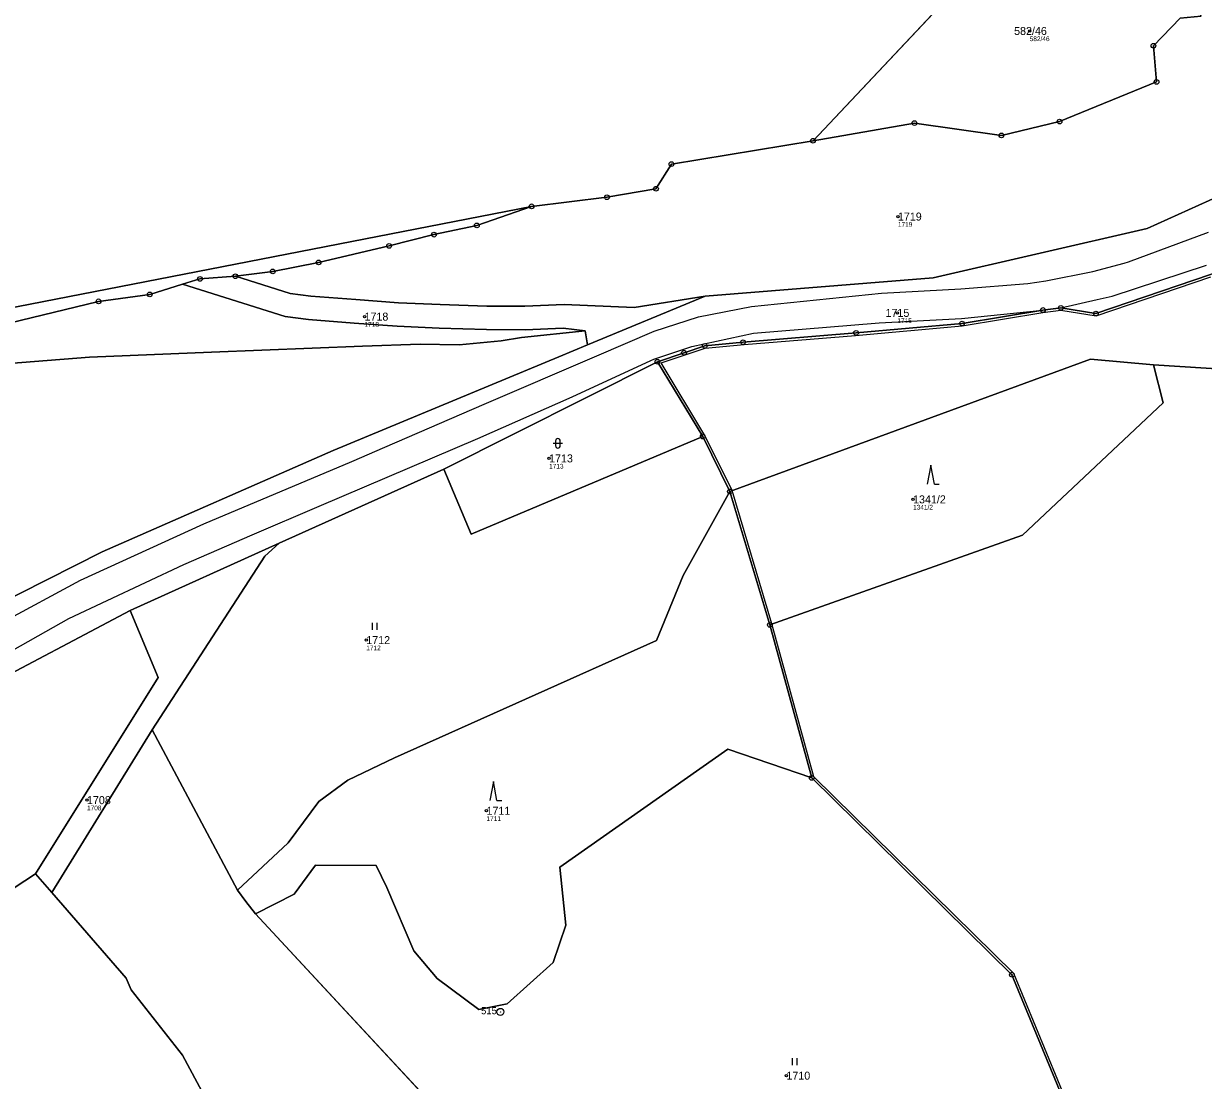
# Model space of a CAD drawing. Extents: x -770088 to -765625, y -1057899 to -1053934.
# Drawn here: x -768436.7 to -768186.2, y -1055836.3 to -1055611.9 of the extents above; entities that cross this region are included whole.
import ezdxf

# ---------------------------------------------------------------- set-up
doc = ezdxf.new("R2010")
doc.units = 0
for name, color, linetype in [('Definiční body', 7, 'Continuous'), ('Hranice parcel', 7, 'Continuous'), ('Parcelní čísla', 7, 'Continuous'), ('Polygon parcely', 7, 'Continuous'), ('Vnitřní kresba', 7, 'Continuous'), ('Značky bodu BP', 7, 'Continuous'), ('Značky kultur', 7, 'Continuous')]:
    doc.layers.add(name, color=color, linetype=linetype)

msp = doc.modelspace()

# ---------------------------------------------------------------- linework, layer by layer
at = {"layer": 'Definiční body'}
for centre in [(-768223.09, -1055613.47), (-768251.07, -1055652.87), (-768251.19, -1055673.32), (-768364.33, -1055674.11), (-768325.14, -1055704.21), (-768247.85, -1055712.91), (-768363.96, -1055742.79), (-768423.26, -1055776.76), (-768338.43, -1055779.02), (-768274.74, -1055835.25)]:
    msp.add_circle(centre, 0.25, dxfattribs=at)
at = {"layer": 'Hranice parcel'}
for p, q in [((-768269.09, -1055636.77), (-768215.72, -1055580.12)), ((-768498.28, -1055683.72), (-768328.85, -1055650.7)), ((-768292.03, -1055669.76), (-768317.01, -1055680.13)), ((-768317.01, -1055680.13), (-768317.48, -1055677.12)), ((-768302.12, -1055683.68), (-768347.5, -1055706.52)), ((-768292.5, -1055699.58), (-768302.12, -1055683.68)), ((-768286.73, -1055711.22), (-768292.5, -1055699.58)), ((-768347.5, -1055706.52), (-768382.42, -1055722.23)), ((-768278.26, -1055739.56), (-768286.73, -1055711.22)), ((-768382.42, -1055722.23), (-768414.12, -1055736.49)), ((-768269.37, -1055772.05), (-768278.26, -1055739.56)), ((-768430.74, -1055796.35), (-768409.4, -1055761.83)), ((-768391.29, -1055795.86), (-768409.4, -1055761.83)), ((-768430.74, -1055796.35), (-768434.17, -1055792.4)), ((-768284.6, -1055911.68), (-768387.49, -1055800.93))]:
    msp.add_line(p, q, dxfattribs=at)
for points in [[(-768196.77, -1055684.34), (-768179.99, -1055685.43), (-768149.61, -1055682.54), (-768104.29, -1055637.41), (-768086.16, -1055607.62), (-767983.52, -1055552.84)], [(-768112.56, -1055604.82), (-768160.87, -1055638.55), (-768198.11, -1055655.41), (-768243.55, -1055665.87), (-768292.03, -1055669.76)], [(-768186.69, -1055610.35), (-768191.13, -1055610.78), (-768196.8, -1055616.6), (-768196.16, -1055624.27), (-768216.73, -1055632.69), (-768229.08, -1055635.64), (-768247.55, -1055633.03), (-768269.09, -1055636.77)], [(-768269.09, -1055636.77), (-768299.15, -1055641.74), (-768302.44, -1055646.96), (-768312.87, -1055648.77), (-768328.85, -1055650.7)], [(-768328.85, -1055650.7), (-768340.48, -1055654.76), (-768349.59, -1055656.71), (-768359.11, -1055659.09), (-768374.07, -1055662.6), (-768383.82, -1055664.53), (-768391.75, -1055665.55)], [(-768391.75, -1055665.55), (-768399.27, -1055666.11), (-768402.98, -1055667.25)], [(-768292.03, -1055669.76), (-768307.07, -1055672.16), (-768321.97, -1055671.56), (-768330.29, -1055671.92), (-768338.37, -1055671.88), (-768348.27, -1055671.57), (-768357.12, -1055671.16), (-768366.16, -1055670.48), (-768375.73, -1055669.74), (-768380.15, -1055669.2), (-768391.75, -1055665.55)], [(-768302.12, -1055683.68), (-768296.49, -1055681.79), (-768292.08, -1055680.32), (-768283.96, -1055679.54), (-768259.94, -1055677.57), (-768237.46, -1055675.58), (-768220.27, -1055672.71), (-768216.46, -1055672.25), (-768209.02, -1055673.46), (-768184.7, -1055665.16)], [(-768402.98, -1055667.25), (-768409.93, -1055669.39), (-768420.8, -1055670.87), (-768439.77, -1055675.5), (-768449.48, -1055677.95), (-768458.49, -1055679.02), (-768472.89, -1055680.73), (-768484.05, -1055683.5), (-768494.16, -1055687.77), (-768494.99, -1055688.26)], [(-768317.48, -1055677.12), (-768322.16, -1055676.57), (-768330.19, -1055676.92), (-768338.46, -1055676.88), (-768348.46, -1055676.57), (-768357.42, -1055676.15), (-768366.53, -1055675.47), (-768376.22, -1055674.72), (-768381.21, -1055674.11), (-768402.98, -1055667.25)], [(-768317.48, -1055677.12), (-768331, -1055678.54), (-768335.32, -1055679.24), (-768344.25, -1055680.07), (-768352.52, -1055679.97), (-768364.76, -1055680.41), (-768396.85, -1055681.68), (-768422.75, -1055682.69), (-768446.13, -1055684.53), (-768460.76, -1055687.94), (-768468.57, -1055690.39), (-768479.04, -1055698.34), (-768510.04, -1055705.01), (-768532.57, -1055718.14), (-768547.75, -1055728.13), (-768565.83, -1055739.84), (-768576.52, -1055745.35), (-768590.86, -1055754.31), (-768615.09, -1055773.23), (-768625.74, -1055787.65)], [(-768317.01, -1055680.13), (-768323.05, -1055682.64), (-768370.97, -1055702.51), (-768420.02, -1055724.02), (-768455.1, -1055741.72), (-768489.08, -1055761.49)], [(-768286.73, -1055711.22), (-768210.16, -1055683.15), (-768196.77, -1055684.34)], [(-768196.77, -1055684.34), (-768194.75, -1055692.38), (-768224.62, -1055720.54), (-768278.26, -1055739.56)], [(-768292.5, -1055699.58), (-768341.68, -1055720.27), (-768347.5, -1055706.52)], [(-768286.73, -1055711.22), (-768296.68, -1055729.05), (-768302.3, -1055742.9), (-768357.96, -1055767.75), (-768367.84, -1055772.51), (-768374.05, -1055777.07), (-768380.51, -1055785.79), (-768391.29, -1055795.86)], [(-768409.4, -1055761.83), (-768385.51, -1055724.99), (-768382.42, -1055722.23)], [(-768414.12, -1055736.49), (-768446.8, -1055753.76), (-768482.2, -1055773.7)], [(-768434.17, -1055792.4), (-768408.16, -1055750.72), (-768414.12, -1055736.49)], [(-768269.37, -1055772.05), (-768287.2, -1055765.92), (-768322.86, -1055791.01), (-768321.57, -1055803.27), (-768324.27, -1055811.21), (-768334.05, -1055819.97), (-768340.04, -1055821.2), (-768348.88, -1055814.61), (-768353.84, -1055808.73), (-768359.61, -1055795.29), (-768361.87, -1055790.62), (-768374.77, -1055790.56), (-768379.26, -1055796.69), (-768387.49, -1055800.93)], [(-768284.6, -1055911.68), (-768256.62, -1055887.41), (-768222.04, -1055883.64), (-768196.97, -1055880.9), (-768208.15, -1055859.21), (-768226.85, -1055813.83), (-768269.37, -1055772.05)], [(-768434.17, -1055792.4), (-768525.18, -1055852.08), (-768616.18, -1055911.76)], [(-768387.49, -1055800.93), (-768389.5, -1055798.25), (-768391.29, -1055795.86)], [(-768301.36, -1055926.65), (-768319.56, -1055917.31), (-768324.83, -1055913.94), (-768331.1, -1055909.69), (-768346.54, -1055893.39), (-768362.81, -1055880.26), (-768375.98, -1055868.58), (-768387.42, -1055856.06), (-768394.12, -1055847.36), (-768402.95, -1055830.89), (-768413.85, -1055817.01), (-768414.95, -1055814.57), (-768430.74, -1055796.35)]]:
    msp.add_lwpolyline(points, dxfattribs=at)
at = {"layer": 'Polygon parcely'}
for points in [[(-768521.62, -1055538.69), (-768491.56, -1055616.88), (-768518.64, -1055655.58), (-768498.28, -1055683.72), (-768328.85, -1055650.7), (-768312.87, -1055648.77), (-768302.44, -1055646.96), (-768299.15, -1055641.74), (-768269.09, -1055636.77), (-768215.72, -1055580.12)], [(-768112.56, -1055604.82), (-768160.87, -1055638.55), (-768198.11, -1055655.41), (-768243.55, -1055665.87), (-768292.03, -1055669.76), (-768317.01, -1055680.13), (-768323.05, -1055682.64), (-768370.97, -1055702.51), (-768420.02, -1055724.02), (-768455.1, -1055741.72)], [(-768086.16, -1055607.62), (-768104.29, -1055637.41), (-768149.61, -1055682.54), (-768179.99, -1055685.43), (-768196.77, -1055684.34), (-768194.75, -1055692.38), (-768224.62, -1055720.54), (-768278.26, -1055739.56), (-768269.37, -1055772.05), (-768226.85, -1055813.83), (-768208.15, -1055859.21), (-768196.97, -1055880.9), (-768222.04, -1055883.64), (-768256.62, -1055887.41), (-768284.6, -1055911.68), (-768295.98, -1055921.55), (-768301.36, -1055926.65), (-768324.43, -1055938.67), (-768353.01, -1055951.04), (-768391.65, -1055965.9), (-768431.86, -1055976.92), (-768474.56, -1055997.15)], [(-768103.19, -1055610.16), (-768111.79, -1055616.51), (-768112.75, -1055629.19), (-768123.27, -1055644.97), (-768143.51, -1055660.46), (-768184.7, -1055665.16), (-768209.02, -1055673.46), (-768216.46, -1055672.25), (-768220.27, -1055672.71), (-768237.46, -1055675.58), (-768259.94, -1055677.57), (-768283.96, -1055679.54), (-768292.08, -1055680.32), (-768296.49, -1055681.79), (-768302.12, -1055683.68), (-768292.5, -1055699.58), (-768286.73, -1055711.22), (-768210.16, -1055683.15), (-768196.77, -1055684.34), (-768179.99, -1055685.43), (-768149.61, -1055682.54), (-768104.29, -1055637.41), (-768086.16, -1055607.62)], [(-768446.8, -1055753.76), (-768414.12, -1055736.49), (-768382.42, -1055722.23), (-768347.5, -1055706.52), (-768302.12, -1055683.68), (-768296.49, -1055681.79), (-768292.08, -1055680.32), (-768283.96, -1055679.54), (-768259.94, -1055677.57), (-768237.46, -1055675.58), (-768220.27, -1055672.71), (-768216.46, -1055672.25), (-768209.02, -1055673.46), (-768184.7, -1055665.16), (-768168.5, -1055657.24), (-768135.64, -1055636.25), (-768111.79, -1055616.51), (-768103.19, -1055610.16)], [(-768191.13, -1055610.78), (-768196.8, -1055616.6), (-768196.16, -1055624.27), (-768216.73, -1055632.69), (-768229.08, -1055635.64), (-768247.55, -1055633.03), (-768269.09, -1055636.77), (-768299.15, -1055641.74), (-768302.44, -1055646.96), (-768312.87, -1055648.77), (-768328.85, -1055650.7), (-768340.48, -1055654.76), (-768349.59, -1055656.71), (-768359.11, -1055659.09), (-768374.07, -1055662.6), (-768383.82, -1055664.53), (-768391.75, -1055665.55), (-768380.15, -1055669.2), (-768375.73, -1055669.74), (-768366.16, -1055670.48), (-768357.12, -1055671.16), (-768348.27, -1055671.57), (-768338.37, -1055671.88), (-768330.29, -1055671.92), (-768321.97, -1055671.56), (-768307.07, -1055672.16), (-768292.03, -1055669.76), (-768243.55, -1055665.87), (-768198.11, -1055655.41), (-768160.87, -1055638.55)], [(-768446.13, -1055684.53), (-768422.75, -1055682.69), (-768396.85, -1055681.68), (-768364.76, -1055680.41), (-768352.52, -1055679.97), (-768344.25, -1055680.07), (-768335.32, -1055679.24), (-768331, -1055678.54), (-768317.48, -1055677.12), (-768322.16, -1055676.57), (-768330.19, -1055676.92), (-768338.46, -1055676.88), (-768348.46, -1055676.57), (-768357.42, -1055676.15), (-768366.53, -1055675.47), (-768376.22, -1055674.72), (-768381.21, -1055674.11), (-768402.98, -1055667.25), (-768409.93, -1055669.39), (-768420.8, -1055670.87), (-768439.77, -1055675.5)], [(-768455.1, -1055741.72), (-768420.02, -1055724.02), (-768370.97, -1055702.51), (-768323.05, -1055682.64), (-768317.01, -1055680.13), (-768317.48, -1055677.12), (-768331, -1055678.54), (-768335.32, -1055679.24), (-768344.25, -1055680.07), (-768352.52, -1055679.97), (-768364.76, -1055680.41), (-768396.85, -1055681.68), (-768422.75, -1055682.69), (-768446.13, -1055684.53)], [(-768474.56, -1055997.15), (-768431.86, -1055976.92), (-768391.65, -1055965.9), (-768353.01, -1055951.04), (-768324.43, -1055938.67), (-768301.36, -1055926.65), (-768319.56, -1055917.31), (-768324.83, -1055913.94), (-768331.1, -1055909.69), (-768346.54, -1055893.39), (-768362.81, -1055880.26), (-768375.98, -1055868.58), (-768387.42, -1055856.06), (-768394.12, -1055847.36), (-768402.95, -1055830.89), (-768413.85, -1055817.01), (-768414.95, -1055814.57), (-768430.74, -1055796.35), (-768434.17, -1055792.4), (-768525.18, -1055852.08)]]:
    msp.add_lwpolyline(points, dxfattribs=at)
for points in [[(-768186.69, -1055610.35), (-768195.09, -1055591.48), (-768202.2, -1055590.14), (-768215.72, -1055580.12), (-768269.09, -1055636.77), (-768247.55, -1055633.03), (-768229.08, -1055635.64), (-768216.73, -1055632.69), (-768196.16, -1055624.27), (-768196.8, -1055616.6), (-768191.13, -1055610.78)], [(-768498.28, -1055683.72), (-768494.99, -1055688.26), (-768494.16, -1055687.77), (-768484.05, -1055683.5), (-768472.89, -1055680.73), (-768458.49, -1055679.02), (-768449.48, -1055677.95), (-768439.77, -1055675.5), (-768420.8, -1055670.87), (-768409.93, -1055669.39), (-768402.98, -1055667.25), (-768399.27, -1055666.11), (-768391.75, -1055665.55), (-768383.82, -1055664.53), (-768374.07, -1055662.6), (-768359.11, -1055659.09), (-768349.59, -1055656.71), (-768340.48, -1055654.76), (-768328.85, -1055650.7)], [(-768307.07, -1055672.16), (-768321.97, -1055671.56), (-768330.29, -1055671.92), (-768338.37, -1055671.88), (-768348.27, -1055671.57), (-768357.12, -1055671.16), (-768366.16, -1055670.48), (-768375.73, -1055669.74), (-768380.15, -1055669.2), (-768391.75, -1055665.55), (-768399.27, -1055666.11), (-768402.98, -1055667.25), (-768381.21, -1055674.11), (-768376.22, -1055674.72), (-768366.53, -1055675.47), (-768357.42, -1055676.15), (-768348.46, -1055676.57), (-768338.46, -1055676.88), (-768330.19, -1055676.92), (-768322.16, -1055676.57), (-768317.48, -1055677.12), (-768317.01, -1055680.13), (-768292.03, -1055669.76)], [(-768278.26, -1055739.56), (-768224.62, -1055720.54), (-768194.75, -1055692.38), (-768196.77, -1055684.34), (-768210.16, -1055683.15), (-768286.73, -1055711.22)], [(-768302.12, -1055683.68), (-768347.5, -1055706.52), (-768341.68, -1055720.27), (-768292.5, -1055699.58)], [(-768347.5, -1055706.52), (-768382.42, -1055722.23), (-768385.51, -1055724.99), (-768409.4, -1055761.83), (-768391.29, -1055795.86), (-768380.51, -1055785.79), (-768374.05, -1055777.07), (-768367.84, -1055772.51), (-768357.96, -1055767.75), (-768302.3, -1055742.9), (-768296.68, -1055729.05), (-768286.73, -1055711.22), (-768292.5, -1055699.58), (-768341.68, -1055720.27)], [(-768380.51, -1055785.79), (-768391.29, -1055795.86), (-768389.5, -1055798.25), (-768387.49, -1055800.93), (-768379.26, -1055796.69), (-768374.77, -1055790.56), (-768361.87, -1055790.62), (-768359.61, -1055795.29), (-768353.84, -1055808.73), (-768348.88, -1055814.61), (-768340.04, -1055821.2), (-768334.05, -1055819.97), (-768324.27, -1055811.21), (-768321.57, -1055803.27), (-768322.86, -1055791.01), (-768287.2, -1055765.92), (-768269.37, -1055772.05), (-768278.26, -1055739.56), (-768286.73, -1055711.22), (-768296.68, -1055729.05), (-768302.3, -1055742.9), (-768357.96, -1055767.75), (-768367.84, -1055772.51), (-768374.05, -1055777.07)], [(-768409.4, -1055761.83), (-768385.51, -1055724.99), (-768382.42, -1055722.23), (-768414.12, -1055736.49), (-768408.16, -1055750.72), (-768434.17, -1055792.4), (-768430.74, -1055796.35)], [(-768414.12, -1055736.49), (-768446.8, -1055753.76), (-768482.2, -1055773.7), (-768515.92, -1055792.7), (-768578.63, -1055829.2), (-768625.43, -1055857.79), (-768643.1, -1055869.51), (-768616.18, -1055911.76), (-768525.18, -1055852.08), (-768434.17, -1055792.4), (-768408.16, -1055750.72)], [(-768284.6, -1055911.68), (-768387.49, -1055800.93), (-768389.5, -1055798.25), (-768391.29, -1055795.86), (-768409.4, -1055761.83), (-768430.74, -1055796.35), (-768414.95, -1055814.57), (-768413.85, -1055817.01), (-768402.95, -1055830.89), (-768394.12, -1055847.36), (-768387.42, -1055856.06), (-768375.98, -1055868.58), (-768362.81, -1055880.26), (-768346.54, -1055893.39), (-768331.1, -1055909.69), (-768324.83, -1055913.94), (-768319.56, -1055917.31), (-768301.36, -1055926.65), (-768295.98, -1055921.55)], [(-768324.27, -1055811.21), (-768334.05, -1055819.97), (-768340.04, -1055821.2), (-768348.88, -1055814.61), (-768353.84, -1055808.73), (-768359.61, -1055795.29), (-768361.87, -1055790.62), (-768374.77, -1055790.56), (-768379.26, -1055796.69), (-768387.49, -1055800.93), (-768284.6, -1055911.68), (-768256.62, -1055887.41), (-768222.04, -1055883.64), (-768196.97, -1055880.9), (-768208.15, -1055859.21), (-768226.85, -1055813.83), (-768269.37, -1055772.05), (-768287.2, -1055765.92), (-768322.86, -1055791.01), (-768321.57, -1055803.27)]]:
    msp.add_lwpolyline(points, close=True, dxfattribs=at)
at = {"layer": 'Vnitřní kresba'}
for p, q in [((-768202.09, -1055662.51), (-768185.09, -1055656.21)), ((-768209.67, -1055664.52), (-768203.04, -1055662.76)), ((-768205.54, -1055669.8), (-768185.54, -1055663.21)), ((-768203.04, -1055662.76), (-768202.09, -1055662.51)), ((-768219.68, -1055666.54), (-768209.67, -1055664.52)), ((-768208.97, -1055673.97), (-768184.61, -1055665.65)), ((-768254.53, -1055669.16), (-768237.71, -1055668.18)), ((-768237.71, -1055668.18), (-768223.45, -1055667.07)), ((-768223.45, -1055667.07), (-768219.68, -1055666.54)), ((-768282.14, -1055671.93), (-768254.53, -1055669.16)), ((-768216.46, -1055672.25), (-768208.76, -1055670.51)), ((-768208.76, -1055670.51), (-768205.54, -1055669.8)), ((-768293.42, -1055674.17), (-768282.14, -1055671.93)), ((-768237.56, -1055674.54), (-768220.27, -1055672.71)), ((-768237.42, -1055676.08), (-768220.28, -1055673.21)), ((-768220.28, -1055673.21), (-768216.46, -1055672.76)), ((-768216.46, -1055672.76), (-768208.97, -1055673.97)), ((-768302.85, -1055677.21), (-768293.42, -1055674.17)), ((-768281.72, -1055677.62), (-768255.03, -1055675.43)), ((-768255.03, -1055675.43), (-768237.56, -1055674.54)), ((-768314.99, -1055682.41), (-768302.85, -1055677.21)), ((-768294.82, -1055680.44), (-768281.72, -1055677.62)), ((-768283.72, -1055680.02), (-768260.1, -1055678.09)), ((-768260.1, -1055678.09), (-768237.42, -1055676.08)), ((-768302.88, -1055683.14), (-768294.82, -1055680.44)), ((-768301.37, -1055683.95), (-768292.02, -1055680.82)), ((-768292.02, -1055680.82), (-768283.72, -1055680.02)), ((-768338.93, -1055692.72), (-768314.99, -1055682.41)), ((-768320.27, -1055691.12), (-768303.52, -1055683.42)), ((-768303.52, -1055683.42), (-768302.88, -1055683.14)), ((-768292.06, -1055699.34), (-768301.37, -1055683.95)), ((-768360.04, -1055701.81), (-768338.93, -1055692.72)), ((-768340.27, -1055699.98), (-768320.27, -1055691.12)), ((-768373.93, -1055714.35), (-768340.27, -1055699.98)), ((-768286.26, -1055711.04), (-768292.06, -1055699.34)), ((-768367.03, -1055704.86), (-768360.04, -1055701.81)), ((-768398.43, -1055718.12), (-768367.03, -1055704.86)), ((-768277.81, -1055739.3), (-768286.26, -1055711.04)), ((-768388.21, -1055720.45), (-768373.93, -1055714.35)), ((-768424.65, -1055730.09), (-768398.43, -1055718.12)), ((-768402.69, -1055726.75), (-768388.21, -1055720.45)), ((-768427.09, -1055738.17), (-768402.69, -1055726.75)), ((-768441.44, -1055739.09), (-768424.65, -1055730.09)), ((-768484.09, -1055770.35), (-768427.09, -1055738.17)), ((-768268.93, -1055771.78), (-768277.81, -1055739.3)), ((-768226.43, -1055813.54), (-768268.93, -1055771.78)), ((-768207.68, -1055859.03), (-768226.43, -1055813.54))]:
    msp.add_line(p, q, dxfattribs=at)
at = {"layer": 'Značky bodu BP'}
for centre, radius in [((-768196.8, -1055616.6), 0.5), ((-768196.8, -1055616.6), 0.0303), ((-768196.16, -1055624.27), 0.5), ((-768196.16, -1055624.27), 0.0303), ((-768247.55, -1055633.03), 0.5), ((-768247.55, -1055633.03), 0.0303), ((-768216.73, -1055632.69), 0.5), ((-768216.73, -1055632.69), 0.0303), ((-768229.08, -1055635.64), 0.5), ((-768229.08, -1055635.64), 0.0303), ((-768269.09, -1055636.77), 0.5), ((-768269.09, -1055636.77), 0.0303), ((-768299.15, -1055641.74), 0.5), ((-768299.15, -1055641.74), 0.0303), ((-768312.87, -1055648.77), 0.5), ((-768302.44, -1055646.96), 0.5), ((-768302.44, -1055646.96), 0.0303), ((-768328.85, -1055650.7), 0.5), ((-768328.85, -1055650.7), 0.0303), ((-768312.87, -1055648.77), 0.0303), ((-768340.48, -1055654.76), 0.5), ((-768340.48, -1055654.76), 0.0303), ((-768349.59, -1055656.71), 0.5), ((-768349.59, -1055656.71), 0.0303), ((-768359.11, -1055659.09), 0.5), ((-768359.11, -1055659.09), 0.0303), ((-768374.07, -1055662.6), 0.5), ((-768374.07, -1055662.6), 0.0303), ((-768399.27, -1055666.11), 0.5), ((-768391.75, -1055665.55), 0.5), ((-768391.75, -1055665.55), 0.0303), ((-768383.82, -1055664.53), 0.5), ((-768383.82, -1055664.53), 0.0303), ((-768399.27, -1055666.11), 0.0303), ((-768420.8, -1055670.87), 0.5), ((-768420.8, -1055670.87), 0.0303), ((-768409.93, -1055669.39), 0.5), ((-768409.93, -1055669.39), 0.0303), ((-768220.27, -1055672.71), 0.5), ((-768220.27, -1055672.71), 0.0303), ((-768216.46, -1055672.25), 0.5), ((-768216.46, -1055672.25), 0.0303), ((-768209.02, -1055673.46), 0.5), ((-768209.02, -1055673.46), 0.0303), ((-768237.46, -1055675.58), 0.5), ((-768237.46, -1055675.58), 0.0303), ((-768259.94, -1055677.57), 0.5), ((-768259.94, -1055677.57), 0.0303), ((-768292.08, -1055680.32), 0.5), ((-768292.08, -1055680.32), 0.0303), ((-768283.96, -1055679.54), 0.5), ((-768283.96, -1055679.54), 0.0303), ((-768302.12, -1055683.68), 0.5), ((-768296.49, -1055681.79), 0.5), ((-768296.49, -1055681.79), 0.0303), ((-768302.12, -1055683.68), 0.0303), ((-768292.5, -1055699.58), 0.5), ((-768292.5, -1055699.58), 0.0303), ((-768286.73, -1055711.22), 0.5), ((-768286.73, -1055711.22), 0.0303), ((-768278.26, -1055739.56), 0.5), ((-768278.26, -1055739.56), 0.0303), ((-768269.37, -1055772.05), 0.5), ((-768269.37, -1055772.05), 0.0303), ((-768226.85, -1055813.83), 0.5), ((-768226.85, -1055813.83), 0.0303), ((-768335.48, -1055821.71), 0.75), ((-768335.48, -1055821.71), 0.03)]:
    msp.add_circle(centre, radius, dxfattribs=at)
at = {"layer": 'Značky kultur'}
for p, q in [((-768324.28, -1055701.01), (-768322.28, -1055701.01)), ((-768323.78, -1055700.51), (-768323.78, -1055701.51)), ((-768322.78, -1055701.51), (-768322.78, -1055700.51)), ((-768244.08, -1055705.67), (-768244.83, -1055709.67)), ((-768243.33, -1055709.67), (-768244.08, -1055705.67)), ((-768243.33, -1055709.67), (-768242.33, -1055709.67)), ((-768362.62, -1055740.59), (-768362.62, -1055739.09)), ((-768361.62, -1055740.59), (-768361.62, -1055739.09)), ((-768336.95, -1055772.82), (-768337.7, -1055776.82)), ((-768336.2, -1055776.82), (-768336.95, -1055772.82)), ((-768336.2, -1055776.82), (-768335.2, -1055776.82)), ((-768273.44, -1055833.05), (-768273.44, -1055831.55)), ((-768272.44, -1055833.05), (-768272.44, -1055831.55))]:
    msp.add_line(p, q, dxfattribs=at)
for centre, start, end in [((-768323.28, -1055700.51), 0, 180), ((-768323.28, -1055701.51), 180, 359.9879)]:
    msp.add_arc(centre, 0.5, start, end, dxfattribs=at)

# ---------------------------------------------------------------- texts
at = {"layer": 'Definiční body'}
for s, p in [('582/46', (-768223.09, -1055615.63)), ('1719', (-768251.07, -1055655.03)), ('1718', (-768364.33, -1055676.27)), ('1715', (-768251.19, -1055675.48)), ('1713', (-768325.14, -1055706.37)), ('1341/2', (-768247.85, -1055715.07)), ('1712', (-768363.96, -1055744.95)), ('1708', (-768423.26, -1055778.92)), ('1711', (-768338.43, -1055781.18))]:
    msp.add_text(s, height=1, dxfattribs=at).set_placement(p)
at = {"layer": 'Parcelní čísla'}
for s, p in [('582/46', (-768226.4, -1055614.32)), ('1719', (-768251.07, -1055653.72)), ('1718', (-768364.33, -1055674.96)), ('1715', (-768253.7, -1055674.17)), ('1713', (-768325.14, -1055705.06)), ('1341/2', (-768247.85, -1055713.76)), ('1712', (-768363.96, -1055743.64)), ('1708', (-768423.26, -1055777.61)), ('1711', (-768338.43, -1055779.87)), ('1710', (-768274.74, -1055836.1))]:
    msp.add_text(s, height=1.7, dxfattribs=at).set_placement(p)
at = {"layer": 'Značky bodu BP'}
msp.add_text('515', height=1.5, dxfattribs=at).set_placement((-768339.58, -1055822.21))

doc.saveas('drawing.dxf')
